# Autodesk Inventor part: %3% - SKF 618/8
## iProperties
IsCustomPart: 1
Created: 2007-02
Part Number: %3% - SKF 618/8
Material: Steel, Mild
Description: Single row ball bearings
Document SubType Name: Modeling
Standard: STN 024630 SKF
Designer: Autodesk, Inc.
Standards Organization: STN
Language: en-US
Size Designation: SKF 618/8
Categories: <MemberInstance><Categories><Category DisplayName="Shaft Parts" InternalName="7f7aeb1f-a693-4053-b835-cee3144e0d98" Mnemonic="SHFT"><Category DisplayName="Beari
Density: 7.86 g/cm^3
Mass: 3.09757 g
Surface Area: 9.49524 cm^2
Volume: 0.394093 cm^3
Author: Autodesk, Inc.
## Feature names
1. Revolution1
2. Revolution2
3. Revolution3
4. PolarArray1 [Circular Pattern]
5. Fillet1
